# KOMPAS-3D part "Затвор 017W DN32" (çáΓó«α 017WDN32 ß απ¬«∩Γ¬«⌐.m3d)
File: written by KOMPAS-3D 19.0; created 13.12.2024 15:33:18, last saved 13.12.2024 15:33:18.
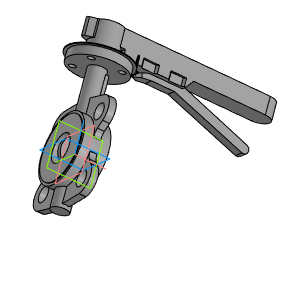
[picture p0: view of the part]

Document properties: Автор: Евгений; Полное имя файла: ..\Затвор 017WDN32.a3d

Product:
- Part/product: Затвор 017W DN32
    Масса: 2.90216

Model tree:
1. Операция без истории:1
